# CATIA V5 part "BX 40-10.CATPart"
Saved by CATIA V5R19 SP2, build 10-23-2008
Part number: BX 40-10
Bounding box of the stored display mesh (mm): x -12.497 to 12.497, y -12.358 to 12.358, z 0 to 75
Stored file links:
  C:\Users\Bora\Desktop\3D Katı model\BX serisi\BX 40\BX 40-10\BX 40-10.CATPart
  C:\Program Files\Dassault Systemes\B19\intel_a\startup\materials\Catalog.CATMaterial
  C:\Program Files\Dassault Systemes\B19\intel_a\reffiles\standard\MetricThickPitch.txt
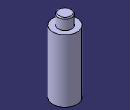
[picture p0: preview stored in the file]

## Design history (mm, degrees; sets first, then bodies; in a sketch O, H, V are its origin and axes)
Body1 (main body)
  Sketch1 on yz-plane, origin (0, 0, 0), H (0, 1, 0), V (0, 0, 1)
    point P1 (7, 74)
    point P3 (7, 74)
    arc A1 centre (6, 74) radius 1 from (7, 74) to (6, 75) ccw
    line L1 (7, 74) -> (7, 64)
    line L2 (12.5, 64) -> (12.5, 0)
    line L3 (0, 75) -> (6, 75)
    line L4 (0, 0) -> (12.5, 0)
    line L5 (7, 64) -> (12.5, 64)
    distance L3 L4 = 75
    length L2 = 64
    length L1 = 10
    length L3 = 6
    distance L1 V = 7
    distance L2 V = 12.5
    radius A1 = 1
    horizontal: L3 H, L4 H, L5 H
    coincidence: P1 P3
  Shaft1: profile Sketch1, axis Sketch1.V, angle 360
  Sketch2 on face of Shaft1 from Sketch1.L4, origin (0, 0, 0), H (1, 0, 0), V (0, -1, 0)
    point P1 (6, 0)
    point P2 (6, 0)
    distance P1 V = 6
  Hole1: placed by Sketch2, at (6, 0, 0) direction (0, 0, 1), diameter 3.242, depth 5, threaded "M4", thread diameter 4, thread depth 5, pitch 0.7
  Sketch3 on face of Shaft1 from Sketch1.L4, origin (0, 0, 0), H (1, 0, 0), V (0, -1, 0)
    point P1 (-6, 0)
    distance P1 V = 6
    distance H P1 = 0
  Hole2: placed by Sketch3, at (-6, 0, 0) direction (0, 0, 1), diameter 3.242, depth 5, threaded "M4", thread diameter 4, thread depth 5, pitch 0.7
